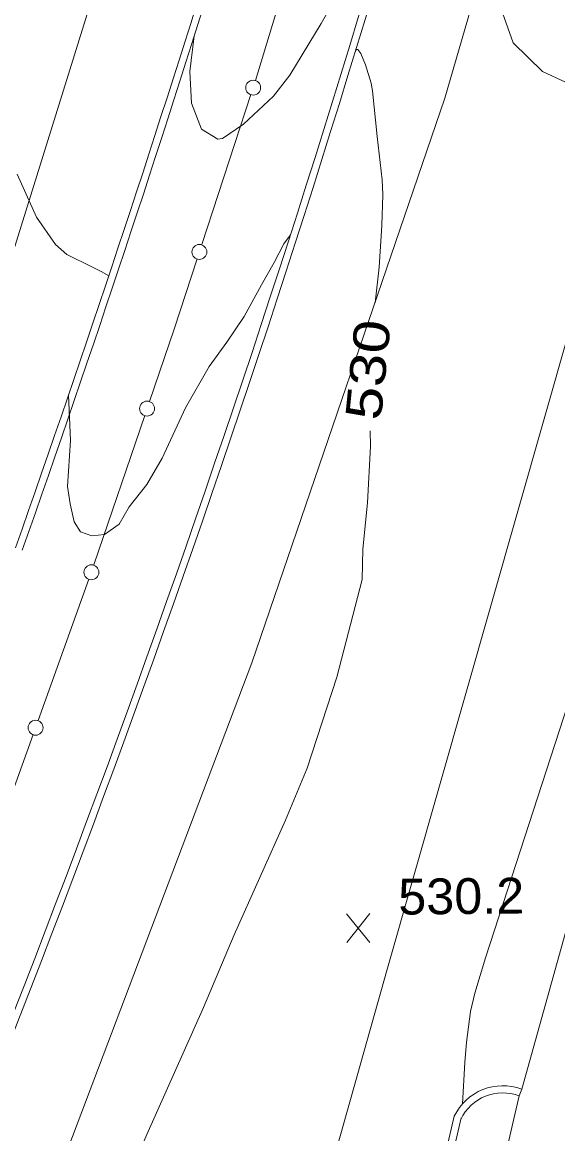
# Model space of a CAD drawing. Extents: x 2361284 to 2366480, y 6976556 to 6985346.
# Drawn here: x 2364924.1 to 2364995.7, y 6979935.6 to 6980084.5 of the extents above; entities that cross this region are included whole.
import ezdxf
from ezdxf.enums import TextEntityAlignment as Align

# ---------------------------------------------------------------- set-up
doc = ezdxf.new("R2010")
doc.units = 0
doc.header["$LTSCALE"] = 1.9
for name, color, linetype, lineweight in [('12', 7, 'Continuous', 13), ('13', 7, 'Continuous', 13), ('14', 7, 'Continuous', 13), ('3', 7, 'Continuous', 13), ('5', 7, 'Continuous', 13)]:
    doc.layers.add(name, color=color, linetype=linetype, lineweight=lineweight)

msp = doc.modelspace()

# ---------------------------------------------------------------- linework, layer by layer
at = {"layer": '12'}
for p, q in [((2364970.615, 6979961.257), (2364967.498, 6979965.108)), ((2364967.535, 6979961.228), (2364970.578, 6979965.137))]:
    msp.add_line(p, q, dxfattribs=at)
for points in [[(2364971.325, 6980046.926), (2364971.839, 6980051.711), (2364972.196, 6980057.315), (2364972.329, 6980061.392), (2364972.228, 6980063.426), (2364971.583, 6980069.241), (2364970.955, 6980075.334), (2364970.771, 6980076.347), (2364970.036, 6980078.826), (2364969.378, 6980080.35), (2364968.992, 6980080.857), (2364968.835, 6980080.888), (2364968.665, 6980080.593)], [(2364935.668, 6980050.577), (2364934.662, 6980051.158), (2364933.296, 6980051.795), (2364930.031, 6980053.394), (2364928.527, 6980054.77), (2364925.984, 6980058.426), (2364923.389, 6980064.181)], [(2364959.967, 6980056.039), (2364959.078, 6980054.86), (2364957.792, 6980052.338), (2364956.111, 6980049.362), (2364953.781, 6980045.128), (2364951.474, 6980041.686), (2364949.115, 6980038.415), (2364945.947, 6980032.874), (2364942.801, 6980026.124), (2364940.764, 6980022.604), (2364938.372, 6980019.591), (2364937.034, 6980017.278), (2364935.087, 6980015.909), (2364933.379, 6980015.713), (2364931.884, 6980016.279), (2364931.021, 6980017.601), (2364930.488, 6980020.026), (2364930.116, 6980022.332), (2364930.527, 6980028.508), (2364930.279, 6980034.626)], [(2365021.691, 6980043.414), (2365017.458, 6980037.375), (2365013.845, 6980033.47), (2365011.673, 6980030.404), (2365010.669, 6980028.823), (2365009.269, 6980026.39), (2365007.418, 6980022.597), (2365004.206, 6980014.947), (2365002.728, 6980011.086), (2365000.733, 6980005.214), (2364997.136, 6979993.248), (2364986.089, 6979959.192), (2364984.634, 6979954.441), (2364984.088, 6979952.012), (2364983.529, 6979947.902), (2364983.301, 6979945.152), (2364982.996, 6979939.641)], [(2364914.517, 6979878.067), (2364915.905, 6979881.39), (2364919.701, 6979889.316), (2364922.931, 6979895.638), (2364926.289, 6979903.2), (2364931.29, 6979913.599), (2364935.167, 6979922.346), (2364940.732, 6979935.519), (2364948.331, 6979952.542), (2364952.439, 6979962.282), (2364959.332, 6979977.628), (2364962.226, 6979984.607), (2364966.181, 6979996.814), (2364969.567, 6980009.868), (2364969.668, 6980013.958), (2364970.309, 6980020.164), (2364970.687, 6980027.739), (2364970.648, 6980029.799)]]:
    msp.add_lwpolyline(points, dxfattribs=at)
at = {"layer": '13'}
for points in [[(2364975.591, 6980107.27), (2364972.805, 6980102.623), (2364967.698, 6980090.725), (2364964.099, 6980084.379), (2364959.873, 6980077.449), (2364957.69, 6980074.628), (2364953.696, 6980070.88), (2364950.884, 6980068.974), (2364950.235, 6980068.888), (2364948.062, 6980070.216), (2364946.729, 6980073.684), (2364946.519, 6980077.942), (2364947.104, 6980082.708)], [(2365020.634, 6980085.097), (2365018.46, 6980083.476), (2365014.62, 6980081.31), (2365008.566, 6980078.702), (2365002.123, 6980076.721), (2364999.747, 6980076.328), (2364996.785, 6980076.52), (2364993.691, 6980077.95), (2364989.765, 6980081.753), (2364987.401, 6980088.461)]]:
    msp.add_lwpolyline(points, dxfattribs=at)
at = {"layer": '14'}
for points in [[(2364488.166, 6979335.073), (2364531.387, 6979380.536), (2364585.832, 6979443.358), (2364610.525, 6979474.004), (2364658.18, 6979536.621), (2364706.572, 6979606.155), (2364727.555, 6979638.679), (2364767.485, 6979704.969), (2364787.631, 6979741.015), (2364825.518, 6979814.358), (2364859.052, 6979886.107), (2364874.641, 6979922.53), (2364903.701, 6979996.656), (2364916.752, 6980034.257), (2364950.998, 6980144.338), (2364960.936, 6980179.186)], [(2365007.099, 6980165.523), (2364980.625, 6980074.346), (2364954.823, 6979998.696), (2364928.454, 6979929.011), (2364895.715, 6979852.887), (2364859.717, 6979777.84), (2364824.691, 6979711.963), (2364785.746, 6979644.97), (2364742.17, 6979575.951), (2364695.149, 6979508.5), (2364647.665, 6979445.756), (2364622.953, 6979415.12), (2364597.396, 6979384.838), (2364544.659, 6979325.73), (2364510.437, 6979289.982)], [(2365030.131, 6980158.041), (2365004.307, 6980067.892), (2364972.982, 6979957.817), (2364943.554, 6979853.382), (2364907.351, 6979725.071), (2364874.382, 6979609.101), (2364864.061, 6979572.294), (2364843.732, 6979498.593), (2364822.126, 6979419.186), (2364811.483, 6979379.439), (2364789.873, 6979297.32), (2364768.994, 6979219.127)]]:
    msp.add_lwpolyline(points, dxfattribs=at)
at = {"layer": '3'}
for p, q in [((2364990.606, 6979940.694), (2364990.947, 6979941.587)), ((2364981.892, 6979937.97), (2364981.892, 6979937.976)), ((2364982.758, 6979937.555), (2364982.828, 6979937.759))]:
    msp.add_line(p, q, dxfattribs=at)
for points in [[(2365053.514, 6980150.563), (2365049.488, 6980138.356), (2365047.491, 6980132.248), (2365044.516, 6980123.08), (2365041.565, 6980113.905), (2365040.098, 6980109.314), (2365037.182, 6980100.126), (2365035.734, 6980095.529), (2365033.572, 6980088.63), (2365029.318, 6980075.001), (2365027.199, 6980068.184), (2365024.042, 6980057.952), (2365021.958, 6980051.125), (2365020.923, 6980047.709), (2365019.383, 6980042.582), (2365017.354, 6980035.739), (2365016.351, 6980032.314), (2365014.862, 6980027.172), (2365013.394, 6980022.023), (2365012.668, 6980019.447), (2365007.345, 6980000.439), (2365003.804, 6979987.765), (2364996.74, 6979962.413), (2364990.947, 6979941.587)], [(2364990.606, 6979940.694), (2364985.099, 6979916.979), (2364974.021, 6979869.563), (2364971.68, 6979859.593), (2364970.109, 6979852.948), (2364966.95, 6979839.664), (2364963.777, 6979826.382), (2364959.549, 6979808.673), (2364957.444, 6979799.816), (2364954.308, 6979786.525), (2364952.753, 6979779.876), (2364951.869, 6979776.027), (2364951.293, 6979773.458), (2364950.167, 6979768.313), (2364949.616, 6979765.739), (2364948.535, 6979760.585), (2364947.473, 6979755.427), (2364945.383, 6979745.103)], [(2364981.892, 6979937.976), (2364931.941, 6979721.793), (2364931.934, 6979721.764)], [(2364982.828, 6979937.759), (2364932.876, 6979721.577), (2364932.656, 6979721.13)]]:
    msp.add_lwpolyline(points, dxfattribs=at)
for centre, radius, start, end in [((2362835.296, 6980750.223), 2213.833, 340.57976, 344.96923), ((2362835.296, 6980750.223), 2214.793, 340.57976, 344.96923), ((2363245.327, 6980606.893), 1800.95, 336.04989, 344.03346), ((2363245.327, 6980606.893), 1801.91, 336.04989, 344.03346), ((2364988.386, 6979934.856), 7.202, 69.16418, 154.37777), ((2364988.386, 6979934.856), 6.242, 69.16419, 154.37777)]:
    msp.add_arc(centre, radius, start, end, dxfattribs=at)
at = {"layer": '5'}
for p, q in [((2364955.291, 6980076.725), (2364961.107, 6980096.002)), ((2364948.119, 6980054.766), (2364954.679, 6980074.829)), ((2364933.676, 6980011.857), (2364940.466, 6980031.842)), ((2364926.195, 6979990.974), (2364933.004, 6980009.92))]:
    msp.add_line(p, q, dxfattribs=at)
for points in [[(2364941.108, 6980033.728), (2364944.407, 6980043.429), (2364947.478, 6980052.82)], [(2364918.18, 6979969.307), (2364921.733, 6979978.531), (2364925.523, 6979989.097)]]:
    msp.add_lwpolyline(points, dxfattribs=at)
for centre in [(2364954.986, 6980075.766), (2364947.782, 6980053.755), (2364940.783, 6980032.771), (2364933.334, 6980010.842), (2364925.861, 6979990.022)]:
    msp.add_circle(centre, 1, dxfattribs=at)

# ---------------------------------------------------------------- texts
at = {"layer": '12', "width": 1.25}
msp.add_text(' 530 ', height=4.799, rotation=84.242, dxfattribs=at).set_placement((2364972.741, 6980037.739), align=Align.CENTER)
at = {"layer": '12', "width": 1.05}
msp.add_text('530.2', height=4.799, rotation=0.545, dxfattribs=at).set_placement((2364974.424, 6979964.981))

doc.saveas('drawing.dxf')
